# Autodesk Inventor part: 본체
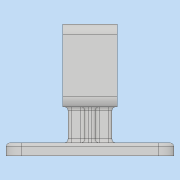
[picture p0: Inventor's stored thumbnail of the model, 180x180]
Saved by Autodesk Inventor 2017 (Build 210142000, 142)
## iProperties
Part Number: 본체
Material: 일반
Document SubType Name: Modeling
Designer: 222
Density: 1 g/cm^3
Appearance: 기본값
Author: 222
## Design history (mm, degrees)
sketch "스케치1"
  geometry: L1 (65, 49)-(-65, 49); L2 (-65, 49)-(-65, -49); L3 (-65, -49)-(65, -49); L4 (65, -49)-(65, 49); L5 (65, 49)-(-65, -49); L6 (-65, 49)-(65, -49); 1 further point
  constraints: 12 end point, 2 midpoint, 2 parallel, 1 horizontal, 1 perpendicular
  dimensions: "d0" = 130 distance of L3.end L2.end; "d1" = 98 distance of L2.end L1.end
extrude "돌출1" new body sketch "스케치1" distance "d2" = 10; taper "d3" = 0 deg
sketch "스케치2"
  geometry: 1 further point
node "작업 평면1"
sketch "스케치3"
  geometry: L1 (30, 38)-(94, 38); L2 (94, 38)-(94, 102); L3 (94, 102)-(30, 102); L4 (30, 102)-(30, 38); L5 (30, 38)-(94, 102); L6 (94, 38)-(30, 102); L7 (0, 0)-(98, 0) reference; L8 (98, 10)-(0, 10) reference; L9 (98, 0)-(98, 10) reference; 4 further points
  constraints: 12 end point, 3 midpoint, 2 parallel, 1 horizontal, 1 perpendicular, 1 point on line, 1 vertical alignment
  dimensions: "d5" = 64 distance of L2.end L3.end; "d6" = 64 distance of L1.end L2.end; "d7" = 70 distance from line of L7 point (62, 70); "d8" = 36 distance from line of L9 point (62, 10)
extrude "돌출2" join sketch "스케치3" distance "d9" = 42; taper "d10" = 0 deg
sketch "스케치4"
  geometry: L1 (-17, -9)-(-17, -17); L2 (-17, -17)-(-4, -17); L3 (-4, -17)-(-4, -33); L4 (-4, -33)-(4, -33); L5 (4, -33)-(4, -17); L6 (4, -17)-(17, -17); L7 (17, -17)-(17, -9); L8 (17, -9)-(4, -9); L9 (4, -9)-(4, 7); L10 (4, 7)-(-4, 7); L11 (-4, 7)-(-4, -9); L12 (-17, -9)-(-4, -9); L13 (65, 49)-(-65, 49) reference; 10 further points
  constraints: 24 end point, 9 midpoint, 8 perpendicular, 7 point on line, 3 vertical alignment, 2 horizontal alignment, 1 vertical
  dimensions: "d11" = 8 distance of L6.end L7.end; "d12" = 8 distance of L9.end L10.end; "d13" = 66 distance from line of L6.end L13; "d15" = 34 distance between parallel lines of L7 L1; "d16" = 17 distance from line of point (0, 0) L1; "d17" = 40 distance between parallel lines of L4 L10; "d18" = 42 distance between parallel lines of L13 L10
extrude "돌출3" join sketch "스케치4" stored distance "d19" = 42; taper "d20" = 0 deg
sketch "스케치5"
  geometry: L1 (66, 10)-(58, 10) reference; L2 (0, 0)-(98, 0) reference; C1 r 21 at (62, 70); 2 further points
  constraints: 1 centre point, 1 midpoint, 1 vertical alignment
  dimensions: "d21" = 42 diameter of C1; "d22" = 70 distance from line of L2 C1.centre
extrude "돌출4" cut sketch "스케치5" distance "d23" = 15; taper "d24" = 0 deg
sketch "스케치6"
  geometry: C1 r 21 at (0, 0) reference; C2 r 18 at (0, 0); 1 further point
  constraints: 1 centre point, 1 coincident
  dimensions: "d25" = 36 diameter of C2
extrude "돌출5" cut sketch "스케치6" distance "d26" = 6; taper "d27" = 0 deg
sketch "스케치7"
  geometry: L1 (-98, 0)-(0, 0) reference; L2 (-58, 10)-(-66, 10) reference; C1 r 21 at (-62, 70); 2 further points
  constraints: 1 centre point, 1 midpoint, 1 vertical alignment
  dimensions: "d28" = 42 diameter of C1; "d29" = 70 distance from line of C1.centre L1
extrude "돌출6" cut sketch "스케치7" distance "d30" = 15; taper "d31" = 0 deg
sketch "스케치8"
  geometry: C1 r 21 at (0, 0) reference; C2 r 18 at (0, 0); 1 further point
  constraints: 1 centre point, 1 coincident
  dimensions: "d32" = 36 diameter of C2
extrude "돌출7" cut sketch "스케치8" distance "d33" = 6; taper "d34" = 0 deg
sketch "스케치9"
  geometry: C1 r 21 at (62, 70) reference; 2 further points
  dimensions: "d35" = 24 horizontal distance of C1.centre point (38, 94); "d36" = 24 horizontal distance of C1.centre point (38, 94)
hole "구멍1" sketch "스케치9" at (38, 94) diameter "d37" = 3.242; stored, may be unused: countersink angle "d41" = 90 deg, drill point angle "d43" = 118 deg; dims "d38" = 8, "d39" = 4, "d40" = 2, "d42" = 10
sketch "스케치10"
  geometry: L1 (65, 49)-(-65, 49) reference; L2 (-65, 49)-(-65, -49) reference; C1 r 4.5 at (-53, 37); 1 further point
  constraints: 1 centre point
  dimensions: "d50" = 9 diameter of C1; "d51" = 12 distance from line of L1 C1.centre; "d52" = 12 distance from line of L2 C1.centre
extrude "돌출8" cut sketch "스케치10" stored distance "d53" = 6; taper "d54" = 0 deg
fillet "모깎기1" dims "d61" = 3
fillet "모깎기2" dims "d62" = 12
fillet "모깎기3" dims "d63" = 8
fillet "모깎기4" dims "d64" = 3
fillet "모깎기5" dims "d65" = 3
chamfer "모따기1" distance "d66" = 1; stored, may be unused: second distance "d67" = 2, angle "d68" = 45 deg
fillet "모깎기6" dims "d69" = 0.3
node "솔리드1"
pattern_linear "직사각형 패턴1" dims "d46" = -48, "d49" = -48
mirror "미러1"
pattern_linear "직사각형 패턴2" dims "d57" = -106, "d60" = -74
other parameters: "d4" = -44
